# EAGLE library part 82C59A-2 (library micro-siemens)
MICROPROCESSOR/PERIPHERAL DEVICE
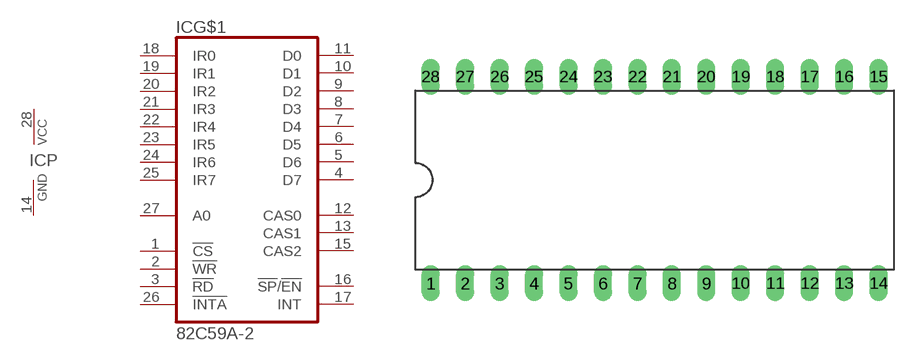
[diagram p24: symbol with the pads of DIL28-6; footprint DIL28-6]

Designator prefix IC; gates G$1=82C59A-2 P=VCCGND

## 82C59A-2 (MPN: CP82C59A-12Z; OC_FARNELL: 1561995; OC_NEWARK: 05M7148)  [DIL28-6]
1  G$1:!CS  in
2  G$1:!WR  in
3  G$1:!RD  in
4  G$1:D7
5  G$1:D6
6  G$1:D5
7  G$1:D4
8  G$1:D3
9  G$1:D2
10  G$1:D1
11  G$1:D0
12  G$1:CAS0
13  G$1:CAS1
14  P:GND  pwr
15  G$1:CAS2
16  G$1:!SP!/!EN
17  G$1:INT  out
18  G$1:IR0  in
19  G$1:IR1  in
20  G$1:IR2  in
21  G$1:IR3  in
22  G$1:IR4  in
23  G$1:IR5  in
24  G$1:IR6  in
25  G$1:IR7  in
26  G$1:!INTA  in
27  G$1:A0  in
28  P:VCC  pwr

## Footprint DIL28-6 (pad centres in mm)
Dual In Line Package 0.6 inch
drill 0.813 long: 1 -16.51,-7.62; 2 -13.97,-7.62; 3 -11.43,-7.62; 4 -8.89,-7.62; 5 -6.35,-7.62; 6 -3.81,-7.62; 7 -1.27,-7.62; 8 1.27,-7.62; 9 3.81,-7.62; 10 6.35,-7.62; 11 8.89,-7.62; 12 11.43,-7.62; 13 13.97,-7.62; 14 16.51,-7.62; 15 16.51,7.62; 16 13.97,7.62; 17 11.43,7.62; 18 8.89,7.62; 19 6.35,7.62; 20 3.81,7.62; 21 1.27,7.62; 22 -1.27,7.62; 23 -3.81,7.62; 24 -6.35,7.62; 25 -8.89,7.62; 26 -11.43,7.62; 27 -13.97,7.62; 28 -16.51,7.62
